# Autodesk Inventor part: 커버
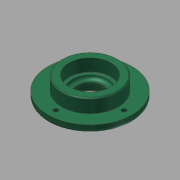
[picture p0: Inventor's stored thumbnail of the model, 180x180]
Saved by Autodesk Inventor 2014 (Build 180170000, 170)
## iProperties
Company: 한국ATC센터
Created: 2014-10
Part Number: 커버
Document SubType Name: Modeling
Designer: KYOUNG IL JANG
Density: 7.86 g/cm^3
Mass: 351.567 g
Surface Area: 161.165 cm^2
Volume: 44.7286 cm^3
Material: 강철, 연강
Appearance: Steel
Author: KYOUNG IL JANG
Revision Number: 1
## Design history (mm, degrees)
sketch "스케치1"
  geometry: C1 r 40 at (0, 0); 1 further point
  constraints: 1 centre point, 1 coincident
  dimensions: "d0" = 80 diameter of C1
extrude "돌출1" new body sketch "스케치1" distance "d1" = 7; taper "d2" = 0 deg
sketch "스케치2"
  geometry: C1 r 27 at (0, 0); 1 further point
  constraints: 1 centre point, 1 coincident
  dimensions: "d3" = 54 diameter of C1
extrude "돌출2" join sketch "스케치2" distance "d4" = 13; taper "d5" = 0 deg
sketch "스케치3"
  geometry: C1 r 20 at (0, 0); 1 further point
  constraints: 1 centre point, 1 coincident
  dimensions: "d6" = 40 diameter of C1
extrude "돌출3" join sketch "스케치3" distance "d7" = 5; taper "d8" = 0 deg
hole "구멍1" diameter "d11" = 25; stored, may be unused: countersink angle "d15" = 90 deg, drill point angle "d17" = 118 deg; dims "d9" = 10, "d10" = 10, "d12" = 6, "d13" = 32, "d14" = 8.3, "d16" = 8
hole "구멍2" diameter "d20" = 34; stored, may be unused: countersink angle "d24" = 90 deg, drill point angle "d26" = 0 deg; dims "d18" = 10, "d19" = 10, "d21" = 6, "d22" = 40, "d23" = 12, "d25" = 3
fillet "모깎기2" dims "d34" = 3
fillet "모깎기1" dims "d27" = 0.3
chamfer "모따기1" distance "d28" = 1; stored, may be unused: second distance "d29" = 2, angle "d30" = 45 deg
chamfer "모따기2" distance "d31" = 1.2; stored, may be unused: second distance "d32" = 2, angle "d33" = 30 deg
sketch "스케치4" dims "d35" = 65
  geometry: 3 further points
  constraints: 2 horizontal alignment, 1 coincident, 2 other
hole "구멍3" sketch "스케치4" at (32.5, 0) diameter "d36" = 4.5; stored, may be unused: countersink angle "d40" = 90 deg, drill point angle "d42" = 118 deg; dims "d37" = 6, "d38" = 8, "d39" = 4.4, "d41" = 13
node "솔리드1"
pattern_circular "원형 패턴1" dims angle "d44" = 360 deg
